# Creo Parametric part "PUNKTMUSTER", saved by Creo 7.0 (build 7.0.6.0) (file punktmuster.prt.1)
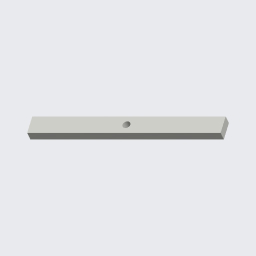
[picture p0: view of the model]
Materials in the file: S235JRG2

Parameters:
  PTC_MATERIAL_NAME = "S235JRG2"
  BENENNUNG = "XXX"
  DATUM = "XX.XX.XX"
  ERSTELLER = "ARINDA"
  TEILETYP = "Fertigungsteil"
  SELECT_EN_NAME = "S235JRG2"
  SELECT_DIN_NAME = "RSt37-2"
  SELECT_DIN_NUMBER = "1.0038"
  SELECT_ASTM_NAME = "A 283 M Grade 2"
  MATERIAL_GROUP = "ME_ST_Baustahl"
  STANDARD_EN_DELIVERYSPEC = "DIN EN 10025"
  STANDARD_DIN_DELIVERYSPEC = "DIN 17100"

Other parameters: MASSE

Created from: ARINDA-STARTTEIL.PRT

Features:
  1. coordinate system "CS0"
  2. datum plane "DTM1", "T_RECHTS_Y-Z"
  3. datum plane "DTM2", "T_OBEN_X-Z"
  4. datum plane "DTM3", "T_VORNE_X-Y"
  5. datum axis "T_X-ACHSE"
  6. datum axis "A_1"
  7. datum axis "A_2"
  8. extrusion "Profil 1"
  9. hole "Bohrung 1"

Other named items: T_BASIC, T_Y-ACHSE, T_Z-ACHSE

Layers: 00_STD-ACHSEN, 00_STD-EBENEN, 00_STD-KOORDSYS, VOLUMENGEOMETRIE

Surfaces: 6 plane, 1 cylinder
